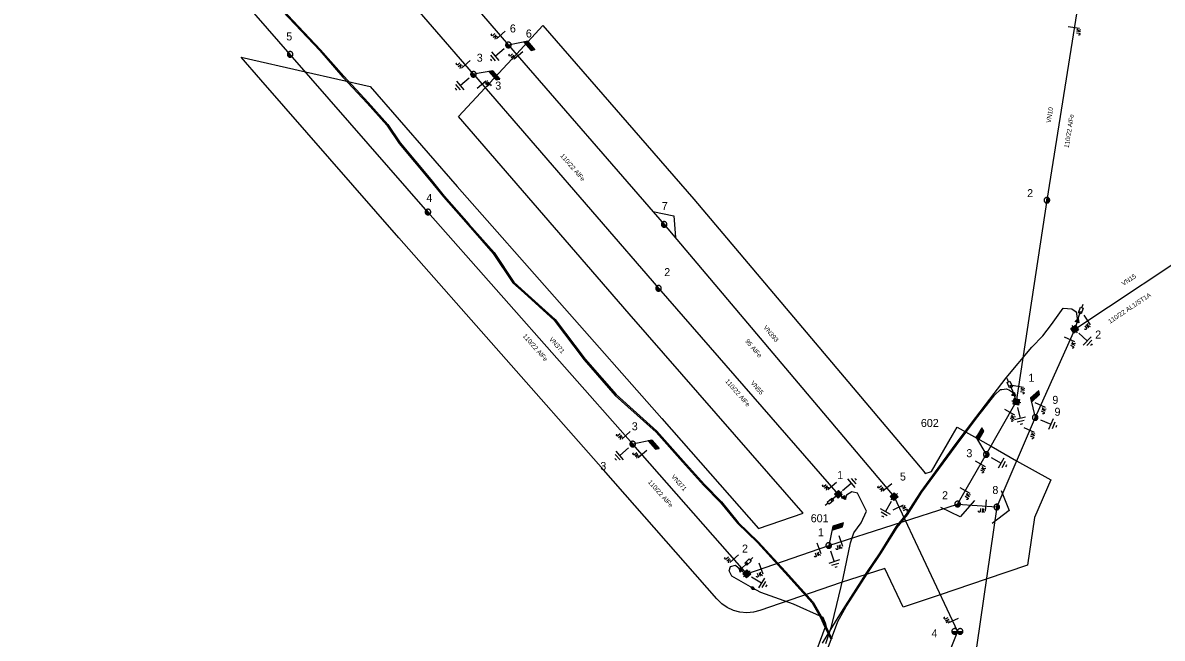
# Model space of a CAD drawing. Extents: x -540879 to -537255, y -1184046 to -1180016.
# Drawn here: x -537632.5 to -537383.5, y -1180474 to -1180339.5 of the extents above; entities that cross this region are included whole.
import ezdxf

# ---------------------------------------------------------------- set-up
doc = ezdxf.new("R2010")
doc.units = 0
for name, color, linetype in [('Default', 7, 'Continuous'), ('Vrstva 1', 7, 'Continuous'), ('Vrstva 11', 7, 'Continuous'), ('Vrstva 12', 7, 'Continuous'), ('Vrstva 13', 7, 'Continuous'), ('Vrstva 14', 7, 'Continuous'), ('Vrstva 15', 7, 'Continuous'), ('Vrstva 16', 7, 'Continuous'), ('Vrstva 18', 7, 'Continuous'), ('Vrstva 19', 7, 'Continuous'), ('Vrstva 2', 7, 'Continuous'), ('Vrstva 3', 7, 'Continuous'), ('Vrstva 35', 7, 'Continuous'), ('Vrstva 4', 7, 'Continuous'), ('Vrstva 5', 7, 'Continuous')]:
    doc.layers.add(name, color=color, linetype=linetype)

# ---------------------------------------------------------------- blocks, each defined once
blk = doc.blocks.new('VN840')
at = {"layer": 'Vrstva 15'}
for points in [[(-0.01, 1.41), (-0.01, -1.09)], [(-1.51, -1.24), (-1.51, -1.15)], [(-1.48, -1.35), (-1.51, -1.24)], [(-1.33, -1.42), (-1.48, -1.35)], [(-1.27, -1.42), (-1.33, -1.42)], [(-1.13, -1.35), (-1.27, -1.42)], [(-1.09, -1.24), (-1.13, -1.35)], [(-1.09, -0.59), (-1.09, -1.24)], [(-0.68, -0.59), (-0.68, -1.42)], [(-0.68, -1.11), (-0.27, -0.59)], [(-0.54, -0.94), (-0.2, -1.42)]]:
    blk.add_lwpolyline(points, dxfattribs=at)
blk = doc.blocks.new('VN860')
at = {"layer": 'Vrstva 15'}
for points in [[(-3.74, 0), (0.01, 2.82)], [(0.01, 2.82), (3.76, 0)]]:
    blk.add_lwpolyline(points, dxfattribs=at)
blk = doc.blocks.new('VN440')
at = {"layer": 'Vrstva 2'}
for points in [[(1.22, 0), (1.21, 0.13), (1.19, 0.25), (1.16, 0.38), (1.11, 0.5), (1.05, 0.61), (0.98, 0.72), (0.9, 0.82), (0.81, 0.91), (0.71, 0.99), (0.6, 1.06), (0.49, 1.12), (0.37, 1.16), (0.25, 1.2), (0.12, 1.22), (-0.01, 1.22), (-0.14, 1.22), (-0.26, 1.2), (-0.39, 1.16), (-0.51, 1.12), (-0.62, 1.06), (-0.73, 0.99), (-0.83, 0.91), (-0.92, 0.82), (-1, 0.72), (-1.07, 0.61), (-1.13, 0.5), (-1.18, 0.38), (-1.21, 0.25), (-1.23, 0.13), (-1.24, 0), (-1.23, -0.13), (-1.21, -0.26), (-1.18, -0.38), (-1.13, -0.5), (-1.07, -0.62), (-1, -0.73), (-0.92, -0.83), (-0.83, -0.92), (-0.73, -1), (-0.62, -1.07), (-0.51, -1.13), (-0.39, -1.17), (-0.26, -1.2), (-0.14, -1.23), (-0.01, -1.23), (0.12, -1.23), (0.25, -1.2), (0.37, -1.17), (0.49, -1.13), (0.6, -1.07), (0.71, -1), (0.81, -0.92), (0.9, -0.83), (0.98, -0.73), (1.05, -0.62), (1.11, -0.5), (1.16, -0.38), (1.19, -0.26), (1.21, -0.13), (1.22, 0)], [(-1.24, 0), (1.22, 0)], [(-1.18, -0.34), (1.1, -0.34)], [(-1.01, -0.63), (0.97, -0.63)], [(-0.74, -0.92), (0.68, -0.92)]]:
    blk.add_lwpolyline(points, dxfattribs=at)
blk = doc.blocks.new('VN870')
at = {"layer": 'Vrstva 4'}
for points in [[(0, -0.25), (0.5, 0), (0, 0.25), (-0.5, 0), (0, -0.25)], [(0.37, 0), (0, 0.19), (-0.36, 0), (0, -0.19), (0.37, 0)], [(0.24, 0), (0, 0.12), (-0.25, 0), (0, -0.12), (0.24, 0)], [(0.12, 0), (0, 0.06), (-0.13, 0), (0, -0.06), (0.12, 0)]]:
    blk.add_lwpolyline(points, dxfattribs=at)
blk = doc.blocks.new('VN890')
at = {"layer": 'Vrstva 4'}
for points in [[(-0.41, 0.41), (0.41, 0)], [(-0.41, -0.41), (-0.41, 0.41)], [(0.41, 0), (-0.41, -0.41)], [(-0.34, 0.31), (0.27, 0), (-0.34, -0.3), (-0.34, 0.31)], [(-0.26, 0.2), (0.1, 0), (-0.26, -0.18), (-0.26, 0.2)], [(-0.19, 0.09), (-0.04, 0), (-0.19, -0.08), (-0.19, 0.09)], [(-0.16, -0.01), (-0.16, 0.03), (-0.13, 0.01), (-0.16, -0.01)]]:
    blk.add_lwpolyline(points, dxfattribs=at)
blk = doc.blocks.new('VN820')
at = {"layer": 'Vrstva 13'}
for points in [[(0, 0), (0, -2.1)], [(-0.32, -1.63), (0.34, -1.63)], [(-0.32, -2.95), (-0.32, -1.63)], [(0, -2.1), (-0.12, -1.86)], [(0, -2.1), (0.12, -1.86)], [(0.34, -1.63), (0.34, -2.95)], [(0.34, -2.95), (-0.32, -2.95)], [(0, -2.95), (0, -3.75)]]:
    blk.add_lwpolyline(points, dxfattribs=at)
blk = doc.blocks.new('VN810')
at = {"layer": 'Vrstva 14'}
for points in [[(0, -1.25), (0, -3.75)], [(1.25, -3.75), (-1.25, -3.75)], [(0.77, -4.37), (-0.8, -4.37)], [(0, -5), (-0.25, -5)], [(0.27, -5), (0, -5)]]:
    blk.add_lwpolyline(points, dxfattribs=at)
blk = doc.blocks.new('VN450')
at = {"layer": 'Vrstva 2'}
for points in [[(0, 0), (-0.01, 0.13), (-0.03, 0.25), (-0.06, 0.38), (-0.11, 0.5), (-0.16, 0.61), (-0.23, 0.72), (-0.31, 0.82), (-0.4, 0.91), (-0.5, 0.99), (-0.61, 1.06), (-0.72, 1.11), (-0.84, 1.16), (-0.97, 1.19), (-1.09, 1.21), (-1.22, 1.22), (-1.35, 1.21), (-1.47, 1.19), (-1.59, 1.16), (-1.71, 1.11), (-1.83, 1.06), (-1.93, 0.99), (-2.03, 0.91), (-2.12, 0.82), (-2.2, 0.72), (-2.27, 0.61), (-2.33, 0.5), (-2.38, 0.38), (-2.41, 0.25), (-2.43, 0.13), (-2.44, 0), (-2.43, -0.13), (-2.41, -0.25), (-2.38, -0.38), (-2.33, -0.5), (-2.27, -0.61), (-2.2, -0.72), (-2.12, -0.82), (-2.03, -0.91), (-1.93, -0.99), (-1.83, -1.06), (-1.71, -1.11), (-1.59, -1.16), (-1.47, -1.19), (-1.35, -1.21), (-1.22, -1.22), (-1.09, -1.21), (-0.97, -1.19), (-0.84, -1.16), (-0.72, -1.11), (-0.61, -1.06), (-0.5, -0.99), (-0.4, -0.91), (-0.31, -0.82), (-0.23, -0.72), (-0.16, -0.61), (-0.11, -0.5), (-0.06, -0.38), (-0.03, -0.25), (-0.01, -0.13), (0, 0)], [(-2.44, 0), (2.44, 0)], [(2.44, 0), (2.43, 0.13), (2.41, 0.25), (2.38, 0.38), (2.33, 0.5), (2.27, 0.61), (2.2, 0.72), (2.12, 0.82), (2.03, 0.91), (1.94, 0.99), (1.83, 1.06), (1.71, 1.11), (1.6, 1.16), (1.47, 1.19), (1.35, 1.21), (1.22, 1.22), (1.09, 1.21), (0.97, 1.19), (0.84, 1.16), (0.72, 1.11), (0.61, 1.06), (0.5, 0.99), (0.4, 0.91), (0.31, 0.82), (0.23, 0.72), (0.16, 0.61), (0.11, 0.5), (0.06, 0.38), (0.03, 0.25), (0.01, 0.13), (0, 0), (0.01, -0.13), (0.03, -0.25), (0.06, -0.38), (0.11, -0.5), (0.16, -0.61), (0.23, -0.72), (0.31, -0.82), (0.4, -0.91), (0.5, -0.99), (0.61, -1.06), (0.72, -1.11), (0.84, -1.16), (0.97, -1.19), (1.09, -1.21), (1.22, -1.22), (1.35, -1.21), (1.47, -1.19), (1.6, -1.16), (1.71, -1.11), (1.83, -1.06), (1.94, -0.99), (2.03, -0.91), (2.12, -0.82), (2.2, -0.72), (2.27, -0.61), (2.33, -0.5), (2.38, -0.38), (2.41, -0.25), (2.43, -0.13), (2.44, 0)], [(-2.4, -0.31), (-0.04, -0.31)], [(-2.26, -0.61), (-0.17, -0.61)], [(-2.01, -0.92), (-0.42, -0.92)], [(0.04, -0.31), (2.4, -0.31)], [(0.17, -0.61), (2.27, -0.61)], [(0.42, -0.92), (2.02, -0.92)]]:
    blk.add_lwpolyline(points, dxfattribs=at)
blk = doc.blocks.new('VN001')
at = {"layer": 'Default'}
for p, q in [((1.73, 3.03), (4.14, 3.03)), ((1.76, 3.08), (4.17, 3.08)), ((1.79, 3.13), (4.2, 3.13)), ((1.82, 3.18), (4.23, 3.18)), ((1.85, 3.23), (4.26, 3.23)), ((1.87, 3.28), (4.29, 3.28)), ((1.9, 3.33), (4.32, 3.33)), ((1.93, 3.38), (4.35, 3.38)), ((1.96, 3.43), (4.37, 3.43)), ((1.99, 3.48), (4.4, 3.48)), ((2.02, 3.53), (4.43, 3.53)), ((2.05, 3.58), (4.46, 3.58)), ((2.07, 3.63), (4.49, 3.63)), ((2.1, 3.68), (4.52, 3.68)), ((2.13, 3.73), (2.54, 3.73))]:
    blk.add_line(p, q, dxfattribs=at)
blk.add_lwpolyline([(2.13, 3.73), (0, 0)], dxfattribs=at)
blk.add_lwpolyline([(4.55, 3.73), (2.13, 3.73), (1.7, 2.98), (4.12, 2.99)], close=True, dxfattribs=at)
blk = doc.blocks.new('VN470')
at = {"layer": 'Vrstva 2'}
for points in [[(-1.23, 1.22), (1.23, 1.22)], [(-1.23, -1.23), (-1.23, 1.22)], [(-0.92, 0.9), (0.92, 0.9)], [(-0.92, -0.95), (-0.92, 0.9)], [(-0.61, 0.61), (0.61, 0.61)], [(-0.61, -0.62), (-0.61, 0.61)], [(-0.31, -0.27), (-0.31, 0.34)], [(-0.31, 0.34), (0.31, 0.34)], [(0, 1.22), (0, 1.97)], [(0.31, 0.34), (0.31, -0.27)], [(0.61, 0.61), (0.61, -0.62)], [(0.92, 0.9), (0.92, -0.95)], [(1.23, 1.22), (1.23, -1.23)], [(1.23, -1.23), (-1.23, -1.23)], [(0.92, -0.95), (-0.92, -0.95)], [(0.61, -0.62), (-0.61, -0.62)], [(0.31, -0.27), (-0.31, -0.27)], [(0, -1.23), (0, -1.98)]]:
    blk.add_lwpolyline(points, dxfattribs=at)

msp = doc.modelspace()

# ---------------------------------------------------------------- linework, layer by layer
at = {"layer": 'Vrstva 1'}
for points in [[(-537534.01, -1180350.75), (-537569.87, -1180309.27), (-537631.69, -1180238), (-537723.88, -1180132.14), (-537744.24, -1180108.87)], [(-537716.13, -1180125.67), (-537714.92, -1180127.04), (-537625.68, -1180229.9), (-537553.13, -1180313.31), (-537526.37, -1180344.35)], [(-537499.2, -1180431.55), (-537543.96, -1180380.85), (-537574.08, -1180346.4), (-537609.27, -1180305.98)], [(-537402.09, -1180337.13), (-537408.66, -1180378.25), (-537415.36, -1180422.31)], [(-537526.37, -1180344.35), (-537492.32, -1180383.55), (-537442.07, -1180443.04)], [(-537534.01, -1180350.75), (-537493.56, -1180397.51), (-537454.26, -1180442.53)], [(-537402.58, -1180406.43), (-537372.88, -1180386.77)], [(-537402.58, -1180406.43), (-537411.23, -1180425.73)], [(-537421.92, -1180433.82), (-537415.36, -1180422.31)], [(-537411.23, -1180425.73), (-537419.62, -1180445.29)], [(-537474.28, -1180459.92), (-537499.2, -1180431.55)], [(-537428.18, -1180444.65), (-537421.92, -1180433.82)], [(-537442.07, -1180443.04), (-537428.24, -1180472.48), (-537455.15, -1180540.11), (-537475.32, -1180590.93), (-537503.35, -1180635.79)], [(-537456.35, -1180453.7), (-537428.18, -1180444.65)], [(-537428.18, -1180444.65), (-537419.62, -1180445.29)], [(-537419.62, -1180445.29), (-537424.74, -1180480.45), (-537431.93, -1180527.5), (-537437.05, -1180560.12)], [(-537474.28, -1180459.92), (-537456.35, -1180453.7)]]:
    msp.add_lwpolyline(points, dxfattribs=at)
at = {"layer": 'Vrstva 35'}
msp.add_lwpolyline([(-537485.86, -1180378.02), (-537435.57, -1180437.57), (-537435.27, -1180438), (-537433.9, -1180437.56), (-537429.3, -1180429.6), (-537428.28, -1180427.82), (-537420.88, -1180432), (-537415.28, -1180435.17), (-537407.83, -1180439.37), (-537411.37, -1180447.62), (-537412.88, -1180458.01), (-537421.92, -1180461.06), (-537432.01, -1180464.47), (-537440.11, -1180467.21), (-537444.11, -1180458.7), (-537453.66, -1180461.76), (-537471.44, -1180467.93), (-537472.8, -1180468.29), (-537474.28, -1180468.42), (-537475.76, -1180468.29), (-537477.19, -1180467.91), (-537478.53, -1180467.28), (-537479.74, -1180466.43), (-537480.66, -1180465.52), (-537480.79, -1180465.38), (-537505.58, -1180437.17), (-537550.34, -1180386.46), (-537580.48, -1180351.99), (-537584.82, -1180347), (-537570.74, -1180350.22), (-537556.63, -1180353.44), (-537537.58, -1180375.23), (-537492.82, -1180425.93), (-537471.67, -1180450.02), (-537461.95, -1180446.65), (-537499.97, -1180403.08), (-537537.27, -1180359.97), (-537531.46, -1180353.7), (-537524.64, -1180346.34), (-537518.83, -1180340.06)], close=True, dxfattribs=at)
at = {"layer": 'Vrstva 5'}
for points in [[(-537578.44, -1180334.06), (-537567.62, -1180345.54), (-537562.55, -1180351.35), (-537557.24, -1180357.05), (-537552.97, -1180361.86), (-537550.26, -1180365.89), (-537543.53, -1180373.91), (-537540.6, -1180377.5), (-537535.19, -1180383.65), (-537529.68, -1180389.87), (-537525.38, -1180396.31), (-537522.93, -1180398.52), (-537516.38, -1180404.49), (-537509.82, -1180413.11), (-537503.02, -1180420.91), (-537494.11, -1180428.94), (-537488.32, -1180435.43), (-537483.71, -1180440.54), (-537480, -1180444.32), (-537476.32, -1180448.83), (-537471.94, -1180453.06), (-537465.95, -1180459.58), (-537459.97, -1180466.26), (-537458.21, -1180469.26), (-537457.18, -1180471.58), (-537455.91, -1180474.15)], [(-537578.25, -1180333.89), (-537567.44, -1180345.37), (-537562.36, -1180351.19), (-537557.06, -1180356.88), (-537552.77, -1180361.71), (-537550.06, -1180365.74), (-537543.33, -1180373.75), (-537540.41, -1180377.34), (-537535, -1180383.48), (-537529.48, -1180389.72), (-537525.19, -1180396.14), (-537522.76, -1180398.33), (-537516.19, -1180404.32), (-537509.63, -1180412.96), (-537502.84, -1180420.74), (-537493.93, -1180428.76), (-537488.13, -1180435.26), (-537483.53, -1180440.37), (-537479.82, -1180444.15), (-537476.13, -1180448.66), (-537471.76, -1180452.89), (-537465.77, -1180459.42), (-537459.77, -1180466.12), (-537457.99, -1180469.15), (-537456.95, -1180471.47), (-537455.67, -1180474.08)], [(-537457.68, -1180475.06), (-537454.68, -1180470.05), (-537452.72, -1180466.87), (-537448.03, -1180459.57), (-537445.14, -1180455.3), (-537441.62, -1180449.65), (-537439.38, -1180446.89), (-537436.17, -1180441.92), (-537428.68, -1180431.73), (-537424.23, -1180425.75), (-537422.05, -1180422.96), (-537417.59, -1180417.07), (-537411.92, -1180410.34), (-537409.58, -1180407.86), (-537407.65, -1180405.4), (-537405.12, -1180401.84), (-537403.24, -1180402), (-537402.27, -1180402.62), (-537401.97, -1180404.53), (-537402.58, -1180406.43)], [(-537456.67, -1180476.61), (-537454.37, -1180470.31), (-537452.51, -1180467), (-537447.82, -1180459.71), (-537444.93, -1180455.44), (-537441.41, -1180449.8), (-537439.17, -1180447.04), (-537435.97, -1180442.07), (-537428.48, -1180431.87), (-537424.04, -1180425.9), (-537421.85, -1180423.11), (-537420.03, -1180420.75), (-537418.8, -1180419.65), (-537418.49, -1180419.6), (-537417.5, -1180419.48), (-537416.82, -1180419.8), (-537416.16, -1180420.23), (-537415.86, -1180420.63), (-537415.36, -1180422.31)], [(-537456.98, -1180475.12), (-537455.77, -1180471.39), (-537454.6, -1180466.62), (-537453.22, -1180460.83), (-537451.58, -1180453.09), (-537450.84, -1180450.95), (-537449.28, -1180448.77), (-537448.13, -1180446.22), (-537450.04, -1180442.26), (-537451.31, -1180441.96), (-537452.47, -1180442.7), (-537452.78, -1180443.66), (-537452.98, -1180443.36), (-537454.26, -1180442.53)], [(-537472.92, -1180463.04), (-537477.57, -1180460.43), (-537478.13, -1180459.22), (-537477.86, -1180458.32), (-537476.73, -1180458.03), (-537475.67, -1180458.92), (-537474.93, -1180459.71), (-537474.28, -1180459.92)], [(-537460.08, -1180479.48), (-537456.89, -1180471.04), (-537457.59, -1180469.44), (-537464.06, -1180466.54), (-537471.21, -1180464.01), (-537472.92, -1180463.04)]]:
    msp.add_lwpolyline(points, dxfattribs=at)

# ---------------------------------------------------------------- block references
at = {"layer": 'Vrstva 11'}
for p, rotation in [((-537526.37, -1180344.35), -49.23628337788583), ((-537534.01, -1180350.75), -49.66940558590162), ((-537411.23, -1180425.73), 42.96217217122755), ((-537499.2, -1180431.55), -48.56020278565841), ((-537421.92, -1180433.82), 60.10080556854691), ((-537456.35, -1180453.7), 17.60429995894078)]:
    msp.add_blockref('VN001', p, dxfattribs=dict(at, rotation=rotation))
at = {"layer": 'Vrstva 13'}
for name, p, xscale, yscale, rotation in [('VN440', (-537526.37, -1180344.35), 0.5000000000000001, 0.5, -49.236330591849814), ('VN440', (-537574.08, -1180346.4), 0.49999999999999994, 0.5000000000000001, -48.956477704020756), ('VN440', (-537534.01, -1180350.75), 0.5, 0.5, -50.22003615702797), ('VN440', (-537408.66, -1180378.25), 0.5, 0.49999999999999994, 81.35403058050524), ('VN440', (-537543.96, -1180380.85), 0.5, 0.49999999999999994, -48.836386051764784), ('VN440', (-537492.32, -1180383.55), 0.5, 0.5, -49.020938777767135), ('VN440', (-537493.56, -1180397.51), 0.5, 0.5, -49.12126115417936), ('VN470', (-537402.58, -1180406.43), 0.5, 0.5, 33.22097505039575), ('VN470', (-537415.36, -1180422.31), 0.5, 0.5, 79.66586668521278), ('VN440', (-537411.23, -1180425.73), 0.5, 0.5000000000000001, 66.80666943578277), ('VN440', (-537499.2, -1180431.55), 0.5, 0.49999999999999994, -48.558261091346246), ('VN440', (-537421.92, -1180433.82), 0.5000000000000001, 0.4999999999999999, 59.972569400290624), ('VN470', (-537454.26, -1180442.53), 0.5, 0.5, 130.68397235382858), ('VN470', (-537442.07, -1180443.04), 0.5, 0.49999999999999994, 131.9542360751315), ('VN440', (-537428.18, -1180444.65), 0.5, 0.5, 17.869624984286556), ('VN440', (-537419.62, -1180445.29), 0.5, 0.5, 81.62706106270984), ('VN440', (-537456.35, -1180453.7), 0.5, 0.5, 18.945997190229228), ('VN470', (-537474.28, -1180459.92), 0.5, 0.5, 131.57130565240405), ('VN450', (-537428.24, -1180472.48), 0.49999999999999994, 0.5, 0.20781114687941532)]:
    msp.add_blockref(name, p, dxfattribs=dict(at, xscale=xscale, yscale=yscale, rotation=rotation))
at = {"layer": 'Vrstva 15'}
for p, rotation in [((-537526.37, -1180344.35), -49.23588055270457), ((-537534.01, -1180350.75), -49.668780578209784), ((-537402.58, -1180406.43), 46.847426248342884), ((-537415.36, -1180422.31), 12.845652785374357), ((-537411.23, -1180425.73), 66.7956305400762), ((-537499.2, -1180431.55), -48.5603693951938), ((-537421.92, -1180433.82), 59.87221949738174), ((-537454.26, -1180442.53), 131.12996184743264), ((-537442.07, -1180443.04), -29.635286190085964), ((-537456.35, -1180453.7), 18.3757360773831), ((-537474.28, -1180459.92), 58.520194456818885)]:
    msp.add_blockref('VN810', p, dxfattribs=dict(at, rotation=rotation))
at = {"layer": 'Vrstva 16'}
for p, rotation in [((-537401.97, -1180404.53), 161.06903336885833), ((-537415.85, -1180420.63), -156.58659721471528), ((-537454.26, -1180442.53), -49.46683891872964), ((-537475.66, -1180458.92), 133.85083332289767)]:
    msp.add_blockref('VN820', p, dxfattribs=dict(at, rotation=rotation))
at = {"layer": 'Vrstva 18'}
for name, p, rotation in [('VN840', (-537528.16, -1180342.28), -49.23719728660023), ('VN840', (-537402.63, -1180340.51), 80.92222220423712), ('VN840', (-537524.29, -1180346.74), -49.02085283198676), ('VN840', (-537535.81, -1180348.67), -49.156424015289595), ('VN840', (-537532.17, -1180352.87), 130.86140306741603), ('VN860', (-537492.32, -1180383.55), -49.019538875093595), ('VN840', (-537399.81, -1180404.58), 33.725644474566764), ('VN840', (-537403.6, -1180408.71), 65.85871940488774), ('VN840', (-537414.84, -1180418.91), 81.35353610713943), ('VN840', (-537410.03, -1180423.05), 65.85871940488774), ('VN840', (-537416.69, -1180424.64), 60.31948883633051), ('VN840', (-537500.78, -1180429.76), -48.56063892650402), ('VN840', (-537412.42, -1180428.5), 66.78373613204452), ('VN840', (-537497.17, -1180433.86), -48.704163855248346), ('VN840', (-537423.13, -1180435.92), 59.97105560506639), ('VN840', (-537455.73, -1180440.85), -48.91367311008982), ('VN840', (-537443.65, -1180441.14), -50.30495268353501), ('VN840', (-537426.48, -1180441.71), 59.97105554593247), ('VN860', (-537419.62, -1180445.29), -105.0409889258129), ('VN840', (-537441.01, -1180445.3), 115.16783056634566), ('VN860', (-537428.18, -1180444.65), -168.46974716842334), ('VN840', (-537422.04, -1180445.11), -4.275841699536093), ('VN840', (-537453.68, -1180452.84), 17.810330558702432), ('VN840', (-537477.12, -1180456.68), -48.704163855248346), ('VN840', (-537458.46, -1180454.43), 19.131897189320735), ('VN840', (-537471.13, -1180458.83), 19.131897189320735), ('VN840', (-537429.3, -1180470.23), -64.832169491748)]:
    msp.add_blockref(name, p, dxfattribs=dict(at, rotation=rotation))
at = {"layer": 'Vrstva 19'}
for name, p, rotation in [('VN890', (-537401.97, -1180404.53), 72.3130056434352), ('VN890', (-537415.86, -1180420.63), 79.61317778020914), ('VN890', (-537452.98, -1180443.36), -50.057248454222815), ('VN890', (-537475.67, -1180458.92), 131.0647944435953), ('VN870', (-537472.96, -1180463.02), -29.34193894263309)]:
    msp.add_blockref(name, p, dxfattribs=dict(at, rotation=rotation))

# ---------------------------------------------------------------- texts
at = {"layer": 'Vrstva 12'}
for s, p in [('6', (-537522.56, -1180342.71)), ('3', (-537529.25, -1180354.09)), ('9', (-537407, -1180425.36)), ('602', (-537436.21, -1180427.81)), ('3', (-537506.29, -1180437.21)), ('601', (-537460.29, -1180448.63))]:
    msp.add_text(s, height=1.75, dxfattribs=at).set_placement(p)
at = {"layer": 'Vrstva 14'}
for s, p in [('6', (-537526.06, -1180341.61)), ('5', (-537574.93, -1180343.34)), ('3', (-537533.3, -1180348)), ('4', (-537544.32, -1180378.63)), ('2', (-537412.99, -1180377.59)), ('7', (-537492.85, -1180380.4)), ('2', (-537492.31, -1180394.85)), ('2', (-537398.1, -1180408.49)), ('1', (-537412.7, -1180417.92)), ('9', (-537407.47, -1180422.76)), ('3', (-537499.41, -1180428.53)), ('3', (-537426.26, -1180434.41)), ('1', (-537454.51, -1180439.19)), ('5', (-537440.79, -1180439.51)), ('2', (-537431.58, -1180443.6)), ('8', (-537420.58, -1180442.44)), ('1', (-537458.71, -1180451.71)), ('2', (-537475.31, -1180455.25)), ('4', (-537433.89, -1180473.76))]:
    msp.add_text(s, height=1.75, dxfattribs=at).set_placement(p)
at = {"layer": 'Vrstva 2'}
for s, rotation, p in [('110/22 AlFe', 80.922, (-537403.9, -1180366.9)), ('110/22 AlFe', 310.861, (-537515.12, -1180368.59)), ('110/22 AL1/ST1A', 33.726, (-537394.86, -1180405.27)), ('110/22 AlFe', 311.439, (-537523.32, -1180407.99)), ('95 AlFe', 310.184, (-537474.69, -1180409.12)), ('110/22 AlFe', 310.792, (-537479.05, -1180417.85)), ('110/22 AlFe', 311.296, (-537495.94, -1180439.9))]:
    msp.add_text(s, height=1, rotation=rotation, dxfattribs=at).set_placement(p)
at = {"layer": 'Vrstva 3'}
for s, rotation, p in [('VN10', 80.922, (-537407.83, -1180361.43)), ('VN15', 33.726, (-537391.91, -1180397.02)), ('VN393', 310.184, (-537470.71, -1180406.12)), ('VN371', 311.439, (-537517.52, -1180408.69)), ('VN55', 310.792, (-537473.51, -1180418.26)), ('VN371', 311.296, (-537490.84, -1180438.74))]:
    msp.add_text(s, height=1, rotation=rotation, dxfattribs=at).set_placement(p)

doc.saveas('drawing.dxf')
